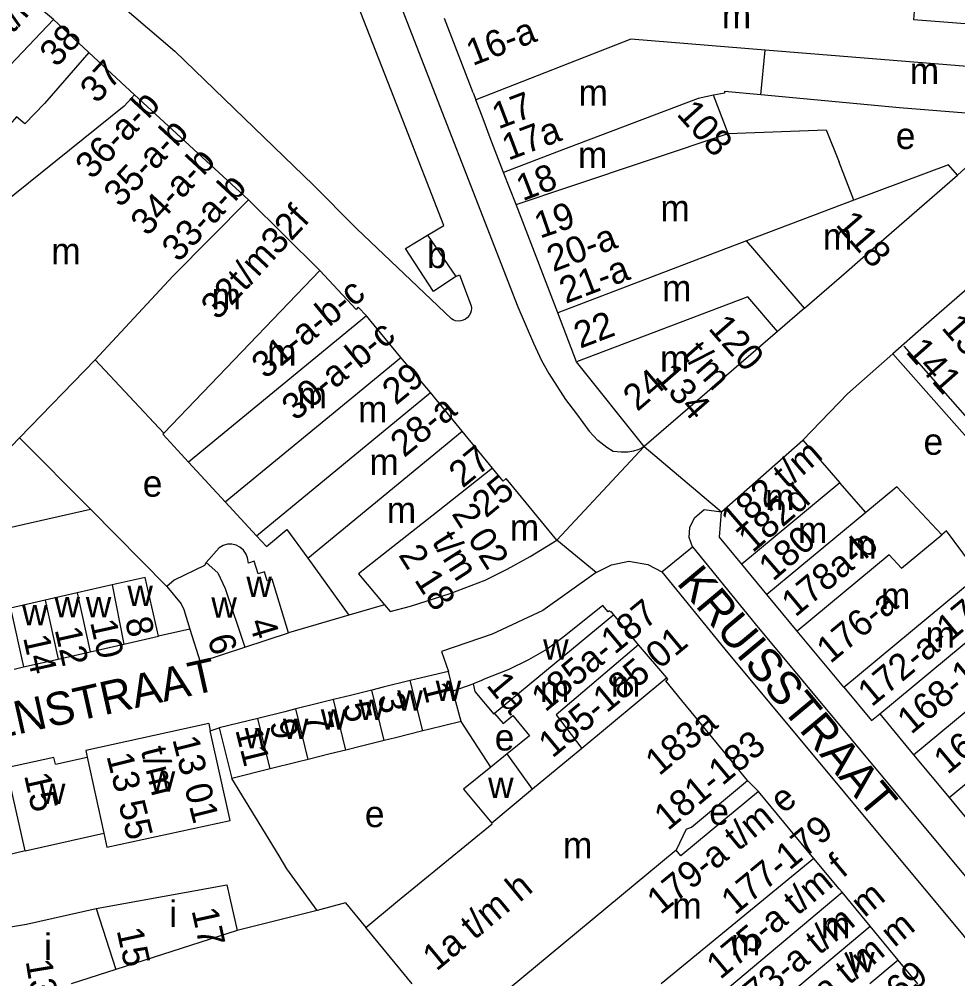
# Model space of a CAD drawing. Extents: x 159902 to 161769, y 383692 to 384875.
# Drawn here: x 160875.8 to 161018, y 384500.8 to 384646.1 of the extents above; entities that cross this region are included whole.
import ezdxf

# ---------------------------------------------------------------- set-up
doc = ezdxf.new("R2010")
doc.units = 0
for name, color, linetype in [('BLT_Basislijn', 7, 'Continuous'), ('BLT_Bebouwing', 7, 'Continuous'), ('BLT_Centroide', 7, 'Continuous'), ('BLT_Huisnummer', 7, 'Continuous'), ('BLT_Huisnummer_ tussenligend', 7, 'Continuous'), ('BLT_Huisnummer_reeks', 7, 'Continuous'), ('BLT_Onderverdeling_panden', 7, 'Continuous'), ('BLT_Plantopo', 7, 'Continuous'), ('BLT_Straatnaam', 7, 'Continuous'), ('BLT_Vlakafsluiter', 7, 'Continuous')]:
    doc.layers.add(name, color=color, linetype=linetype)

msp = doc.modelspace()

# ---------------------------------------------------------------- linework, layer by layer
at = {"layer": 'BLT_Basislijn'}
for p, q in [((160933.92, 384630.81), (160885.35, 384755.32)), ((160928.92, 384660.13), (160951.34, 384602.56)), ((161027.38, 384631.21), (161017.96, 384622.48)), ((160920.37, 384620.98), (160921.06, 384620.29)), ((160921.06, 384620.29), (160921.77, 384619.57)), ((160921.77, 384619.57), (160925.33, 384615.97)), ((160925.33, 384615.97), (160926.92, 384614.36)), ((160941.3, 384600.71), (160926.92, 384614.36)), ((160951.34, 384602.56), (160953.7, 384597.06)), ((160886.59, 384571.89), (160875.82, 384582.68)), ((160849.88, 384563.61), (160886.59, 384571.89)), ((160898.15, 384560.18), (160886.59, 384571.89)), ((160925.7, 384555.85), (160916.6, 384553.15)), ((160901.65, 384553.72), (160896.9, 384552.65)), ((160875.02, 384547.68), (160876.45, 384548.01)), ((160941.52, 384544.37), (160944.55, 384545.43)), ((160947.25, 384532.83), (160942.74, 384539.74)), ((160904.73, 384538.31), (160906.08, 384538.75)), ((160915.18, 384519.36), (160907.97, 384531.12)), ((160986.13, 384530.8), (160987.78, 384529.14)), ((160925.22, 384512.26), (160920.94, 384511.11)), ((160925.22, 384512.26), (160928.28, 384508.51)), ((160920.94, 384511.11), (160908.8, 384508.06))]:
    msp.add_line(p, q, dxfattribs=at)
for points in [[(160886.94, 384651.93), (160899.37, 384641.29), (160920.37, 384620.98)], [(160937.62, 384613.43), (160940.13, 384614.89), (160933.92, 384630.81)], [(160941.91, 384607.15), (160942.48, 384607.42), (160944.24, 384602.72)], [(160944.24, 384602.72), (160944.29, 384602.33), (160944.26, 384601.94), (160944.14, 384601.57), (160943.96, 384601.22), (160943.71, 384600.92), (160943.4, 384600.68), (160943.05, 384600.51), (160942.67, 384600.41), (160942.28, 384600.39), (160941.89, 384600.45), (160941.53, 384600.58), (160941.3, 384600.71)], [(160953.7, 384597.06), (160954.92, 384594.41), (160956.02, 384592.44), (160958.56, 384588.52), (160960.2, 384586.32)], [(161008.13, 384595.45), (161001.28, 384589.38), (160994.52, 384582.33)], [(160960.2, 384586.32), (160962.12, 384583.7), (160962.77, 384582.99), (160963.44, 384582.32)], [(160970.48, 384581.39), (160970, 384581.09), (160969.52, 384580.87), (160968.84, 384580.68), (160967.98, 384580.54), (160966.96, 384580.52), (160965.79, 384580.65), (160964.79, 384581.25), (160963.44, 384582.32)], [(160977.8, 384566.17), (160977.3, 384567.63), (160977.38, 384569.1), (160978.07, 384570.56), (160979.54, 384571.85), (160982.19, 384571.49)], [(160977.8, 384566.17), (160987.31, 384554.52), (161023.67, 384510.86), (161030, 384502.12), (161036.93, 384491.9), (161074.73, 384428.36), (161080.55, 384419.2)], [(160963.19, 384562.31), (160965.5, 384563.49), (160968.16, 384564.03), (160971.04, 384563.52), (160973.15, 384562.38)], [(160963.19, 384562.31), (160955.13, 384556.53), (160947.46, 384552.96), (160939.77, 384550.36), (160940.8, 384547.31)], [(160973.15, 384562.38), (160982.68, 384550.7), (161018.93, 384507.18), (161025.08, 384498.68), (161031.86, 384488.68), (161069.62, 384425.22), (161087.78, 384396.62), (161099.26, 384377.62)], [(160920.94, 384511.11), (160916.33, 384517.4), (160915.18, 384519.36)]]:
    msp.add_lwpolyline(points, dxfattribs=at)
at = {"layer": 'BLT_Bebouwing'}
for p, q in [((160886.34, 384641.08), (160880.96, 384646.06)), ((160893.27, 384634.67), (160886.34, 384641.08)), ((160910.51, 384618.77), (160893.27, 384634.67)), ((160944.57, 384634.97), (160944.94, 384633.91)), ((160983.22, 384628.83), (160980.99, 384634.59)), ((160947.15, 384628.16), (160946.05, 384631.03)), ((160949.17, 384622.92), (160947.15, 384628.16)), ((161002.26, 384618.72), (161000, 384624.44)), ((160951.06, 384618.03), (160949.17, 384622.92)), ((161004.88, 384611.11), (161017.96, 384622.48)), ((160957.37, 384601.64), (160951.06, 384618.03)), ((160937.62, 384613.43), (160941.91, 384607.15)), ((161001.12, 384607.84), (161004.88, 384611.11)), ((161025.93, 384610.96), (161012.86, 384599.57)), ((160941.91, 384607.15), (160938.57, 384604.89)), ((160994.78, 384602.33), (161001.12, 384607.84)), ((160994.78, 384602.33), (160990.69, 384598.83)), ((160928.87, 384600.64), (160928.41, 384601.21)), ((160933.6, 384594.88), (160928.87, 384600.64)), ((161012.86, 384599.57), (161008.13, 384595.45)), ((160990.69, 384598.83), (160970.48, 384581.39)), ((161008.13, 384595.45), (161023.09, 384578.49)), ((160887.31, 384594.51), (160875.82, 384582.68)), ((160897.69, 384583.43), (160887.31, 384594.51)), ((160938.07, 384589.58), (160933.6, 384594.88)), ((160942.9, 384583.7), (160938.07, 384589.58)), ((160947.48, 384578.12), (160942.9, 384583.7)), ((160982.19, 384571.49), (160994.52, 384582.33)), ((160994.52, 384582.33), (161000.13, 384575.89)), ((160906.97, 384573.03), (160901.45, 384579.02)), ((161004.06, 384571.4), (161000.13, 384575.89)), ((160906.97, 384573.03), (160911.71, 384567.88)), ((160911.71, 384567.88), (160913.24, 384566.23)), ((161016.27, 384568.64), (161015.58, 384568.03)), ((161021.22, 384561.97), (161016.27, 384568.64)), ((160989.07, 384558.99), (160985.27, 384563.58)), ((160889.87, 384560.42), (160884.56, 384559.21)), ((160884.56, 384559.21), (160879.71, 384558.11)), ((160993.67, 384553.43), (160989.07, 384558.99)), ((160969.61, 384551.36), (160965.85, 384555.91)), ((160901.65, 384553.72), (160903.21, 384548.76)), ((160909.96, 384550.97), (160916.6, 384553.15)), ((161000.72, 384544.92), (160993.67, 384553.43)), ((160886.55, 384550.3), (160891.63, 384551.45)), ((160881.7, 384549.2), (160886.55, 384550.3)), ((160903.21, 384548.76), (160909.96, 384550.97)), ((160940.8, 384547.31), (160935.88, 384546.15)), ((160941.52, 384544.37), (160940.8, 384547.31)), ((160935.02, 384545.93), (160930.91, 384544.91)), ((160935.88, 384546.15), (160935.02, 384545.93)), ((160929.2, 384544.49), (160925.95, 384543.68)), ((160930.91, 384544.91), (160929.2, 384544.49)), ((160923.38, 384543.04), (160920.98, 384542.45)), ((160925.95, 384543.68), (160923.38, 384543.04)), ((160916.01, 384541.22), (160911.91, 384540.2)), ((160917.68, 384541.63), (160916.01, 384541.22)), ((160920.98, 384542.45), (160917.68, 384541.63)), ((160911.91, 384540.2), (160906.08, 384538.75)), ((160942.74, 384539.74), (160937.77, 384538.51)), ((161006.16, 384540.89), (161011.29, 384534.7)), ((160904.52, 384539.42), (160904.73, 384538.31)), ((160936.92, 384538.3), (160932.81, 384537.28)), ((160937.77, 384538.51), (160936.92, 384538.3)), ((160931.09, 384536.85), (160927.84, 384536.04)), ((160932.81, 384537.28), (160931.09, 384536.85)), ((160925.27, 384535.41), (160922.87, 384534.81)), ((160927.84, 384536.04), (160925.27, 384535.41)), ((160986.13, 384530.8), (160981.58, 384536.35)), ((160881.01, 384534.27), (160873.86, 384532.72)), ((160881.27, 384533.26), (160886.07, 384534.34)), ((160919.56, 384533.99), (160917.91, 384533.58)), ((160922.87, 384534.81), (160919.56, 384533.99)), ((161011.29, 384534.7), (161016.67, 384528.21)), ((160913.82, 384532.57), (160907.97, 384531.12)), ((160917.91, 384533.58), (160913.82, 384532.57)), ((160996.19, 384518.99), (160987.78, 384529.14)), ((161016.67, 384528.21), (161020.45, 384523.64)), ((160976.85, 384523.41), (160975.31, 384520.26)), ((161000, 384514.4), (160996.19, 384518.99)), ((160887.45, 384511.42), (160907.26, 384515)), ((161000.45, 384513.86), (161000, 384514.4)), ((161004.71, 384508.72), (161000.45, 384513.86)), ((160908.8, 384508.06), (160890.42, 384502.17)), ((160935.33, 384500), (160928.28, 384508.51)), ((161008.97, 384503.58), (161004.71, 384508.72)), ((161011.94, 384500), (161008.97, 384503.58)), ((160890.42, 384502.17), (160883.63, 384500))]:
    msp.add_line(p, q, dxfattribs=at)
for points in [[(160973.65, 384653.51), (161011.61, 384650.35), (161011.27, 384646.09), (161023.71, 384645.1), (161023.19, 384638.65)], [(160880.96, 384646.06), (160874.66, 384651.39)], [(160944.57, 384634.97), (160940.23, 384646.21)], [(160988.13, 384634.65), (160982.63, 384635.17), (160982.66, 384634.93), (160980.99, 384634.59)], [(161027.38, 384631.21), (161009.15, 384632.67), (160988.13, 384634.65)], [(160946.05, 384631.03), (160944.94, 384633.91)], [(160983.22, 384628.83), (160998.05, 384629.37), (161000, 384624.44)], [(161017.96, 384622.48), (161016.56, 384624.08), (161002.26, 384618.72)], [(160921.32, 384608.04), (160910.51, 384618.77)], [(160938.57, 384604.89), (160934.3, 384611.38), (160937.62, 384613.43)], [(160928.41, 384601.21), (160927.13, 384602.48), (160926.81, 384602.15), (160921.32, 384608.04)], [(160960.23, 384594.23), (160957.37, 384601.64)], [(160970.48, 384581.39), (160960.23, 384594.23)], [(160901.45, 384579.02), (160897.55, 384583.25), (160897.69, 384583.43)], [(160875.82, 384582.68), (160870.77, 384577.48)], [(160957.23, 384567.18), (160949.55, 384576.54), (160949.09, 384576.16), (160947.48, 384578.12)], [(161015.58, 384568.03), (161008.76, 384575.3), (161004.06, 384571.4)], [(160985.27, 384563.58), (160981.9, 384567.64), (160982.19, 384571.49)], [(160913.24, 384566.23), (160916.35, 384568.84), (160919.51, 384564.45)], [(160916.6, 384553.15), (160914.13, 384561.27), (160913.37, 384561.04), (160912.94, 384562.39), (160911.99, 384562.09), (160911.39, 384564), (160910.51, 384563.72), (160910.37, 384564.54), (160910.17, 384565.09), (160909.76, 384565.7), (160909.23, 384566.16), (160908.63, 384566.46), (160908, 384566.59), (160907.35, 384566.58), (160906.68, 384566.39), (160906.08, 384566.03), (160904.11, 384563.81)], [(160931.14, 384557.43), (160931.96, 384556.42), (160935.07, 384557.21), (160941.08, 384559.1), (160946.38, 384561.16), (160949.72, 384562.81), (160953.22, 384564.72), (160957.23, 384567.18)], [(160919.51, 384564.45), (160925.7, 384555.85)], [(160904.11, 384563.81), (160903.83, 384563.38), (160899.25, 384561.13), (160898.15, 384560.18)], [(160896.9, 384552.65), (160894.87, 384561.55), (160889.87, 384560.42)], [(160898.15, 384560.18), (160900.31, 384557.56), (160900.72, 384556.7), (160901.65, 384553.72)], [(160879.71, 384558.11), (160874.46, 384556.92), (160876.45, 384548.01)], [(160931.14, 384557.43), (160925.7, 384555.85)], [(160964.21, 384557.31), (160958.36, 384552.61), (160955.77, 384550.7), (160952.92, 384549.05), (160949.94, 384547.62), (160945.95, 384546.06), (160945.98, 384545.98), (160944.55, 384545.43)], [(160965.85, 384555.91), (160965.5, 384556.33), (160965.42, 384556.27), (160965.21, 384556.51), (160965.01, 384556.35), (160964.21, 384557.31)], [(160891.63, 384551.45), (160896.9, 384552.65)], [(160973.9, 384546.33), (160969.61, 384551.36)], [(160876.45, 384548.01), (160881.7, 384549.2)], [(160981.58, 384536.35), (160976.17, 384542.93), (160973.74, 384545.87), (160974.06, 384546.14), (160973.9, 384546.33)], [(160942.74, 384539.74), (160941.8, 384543.25), (160941.52, 384544.37)], [(160944.55, 384545.43), (160944.82, 384544.29), (160947.68, 384540.85), (160947.81, 384540.96)], [(161000.72, 384544.92), (161004.92, 384539.86), (161006.16, 384540.89)], [(160947.81, 384540.96), (160949.09, 384539.42), (160950.55, 384540.63), (160953.1, 384537.55)], [(160904.52, 384539.42), (160885.85, 384535.36)], [(160888.6, 384522.81), (160889.07, 384520.68), (160907.74, 384524.73), (160904.73, 384538.31)], [(160906.08, 384538.75), (160907.28, 384533.9), (160907.97, 384531.12)], [(160953.1, 384537.55), (160949.71, 384534.82)], [(160881.27, 384533.26), (160881.01, 384534.27)], [(160885.85, 384535.36), (160886.07, 384534.34)], [(160949.71, 384534.82), (160947.25, 384532.83)], [(160947.25, 384532.83), (160943.11, 384529.49), (160947.38, 384524.35)], [(160976.85, 384523.41), (160977.62, 384523.75), (160986.13, 384530.8)], [(160987.78, 384529.14), (160983.93, 384525.94), (160982.54, 384524.79), (160976.03, 384519.39), (160975.31, 384520.26)], [(160928.28, 384508.51), (160933.09, 384512.5), (160947.46, 384524.25), (160947.38, 384524.35)], [(160876.67, 384520.14), (160888.6, 384522.81)], [(160876.67, 384520.14), (160869.89, 384518.53), (160869.5, 384520.27)], [(160907.26, 384515), (160907.71, 384512.95), (160908.8, 384508.06)], [(160867.05, 384507.42), (160876.87, 384509.04), (160887.45, 384511.42)]]:
    msp.add_lwpolyline(points, dxfattribs=at)
at = {"layer": 'BLT_Onderverdeling_panden'}
for p, q in [((160880.96, 384646.06), (160869.82, 384634.36)), ((160988.13, 384634.65), (160988.81, 384641.43)), ((161023.19, 384638.65), (160988.81, 384641.43)), ((160957.21, 384625.97), (160949.17, 384622.92)), ((160951.06, 384618.03), (160959.19, 384620.76)), ((160910.51, 384618.77), (160899.07, 384607.21)), ((161002.26, 384618.72), (160985.98, 384612.53)), ((160985.98, 384612.53), (160957.37, 384601.64)), ((160994.78, 384602.33), (160985.98, 384612.53)), ((160899.07, 384607.21), (160887.31, 384594.51)), ((160921.32, 384608.04), (160897.69, 384583.43)), ((160928.41, 384601.21), (160901.45, 384579.02)), ((160925.61, 384588.3), (160933.6, 384594.88)), ((160911.71, 384567.88), (160938.07, 384589.58)), ((160906.97, 384573.03), (160925.61, 384588.3)), ((160919.51, 384564.45), (160942.9, 384583.7)), ((161000.13, 384575.89), (160985.27, 384563.58)), ((161004.06, 384571.4), (160989.07, 384558.99)), ((161007.6, 384564.97), (160993.67, 384553.43)), ((161000.72, 384544.92), (161021.22, 384561.97)), ((160889.87, 384560.42), (160891.63, 384551.45)), ((160884.56, 384559.21), (160886.55, 384550.3)), ((160879.71, 384558.11), (160881.7, 384549.2)), ((160965.85, 384555.91), (160947.81, 384540.96)), ((161006.16, 384540.89), (161025.17, 384556.65)), ((161011.29, 384534.7), (161029.57, 384549.91)), ((160936.92, 384538.3), (160935.02, 384545.93)), ((160973.9, 384546.33), (160961, 384535.64)), ((160931.09, 384536.85), (160929.2, 384544.49)), ((160925.27, 384535.41), (160923.38, 384543.04)), ((161016.67, 384528.21), (161034.95, 384543.42)), ((160919.56, 384533.99), (160917.68, 384541.63)), ((160913.82, 384532.57), (160911.91, 384540.2)), ((160961, 384535.64), (160953.57, 384529.48)), ((160953.57, 384529.48), (160949.71, 384534.82)), ((160876.67, 384520.14), (160873.86, 384532.72)), ((160953.57, 384529.48), (160947.38, 384524.35)), ((160975.31, 384520.26), (160947.03, 384496.81)), ((160996.19, 384518.99), (160983.75, 384508.78)), ((160971.34, 384489.46), (161000.45, 384513.86)), ((160887.45, 384511.42), (160890.42, 384502.17)), ((160983.75, 384508.78), (160973.06, 384500)), ((160975.56, 384484.38), (161004.71, 384508.72)), ((161008.97, 384503.58), (161004.65, 384500))]:
    msp.add_line(p, q, dxfattribs=at)
for points in [[(160988.81, 384641.43), (160968.47, 384643.09), (160944.94, 384633.91)], [(160886.34, 384641.08), (160879.61, 384633.33), (160876.63, 384630.26), (160875.38, 384631.33), (160873.47, 384629.1), (160846.06, 384604.07)], [(160893.27, 384634.67), (160891.67, 384632.95), (160850.2, 384599.61)], [(160980.99, 384634.59), (160978.67, 384634.12), (160957.21, 384625.97)], [(160959.19, 384620.76), (160983.22, 384628.83)], [(160990.69, 384598.83), (160986.19, 384604.04), (160960.23, 384594.23)], [(160947.48, 384578.12), (160938.98, 384571.37), (160927.19, 384562.12), (160931.14, 384557.43)], [(161007.6, 384564.97), (161009.47, 384562.97), (161015.58, 384568.03)], [(160904.11, 384563.81), (160905.86, 384562.26), (160907, 384559.86), (160909.96, 384550.97)], [(160969.61, 384551.36), (160957.11, 384540.73), (160961, 384535.64)], [(160886.07, 384534.34), (160888.6, 384522.81)]]:
    msp.add_lwpolyline(points, dxfattribs=at)
at = {"layer": 'BLT_Plantopo'}
msp.add_lwpolyline([(161043.16, 384625.94), (161048.23, 384620.2), (161039.91, 384612.87), (161046.32, 384605.59), (161021.33, 384583.57), (161009.86, 384596.59)], dxfattribs=at)
at = {"layer": 'BLT_Vlakafsluiter'}
for p, q in [((160957.23, 384567.18), (160970.48, 384581.39)), ((160970.48, 384581.39), (160982.19, 384571.49)), ((160963.19, 384562.31), (160957.23, 384567.18)), ((160973.15, 384562.38), (160977.8, 384566.17))]:
    msp.add_line(p, q, dxfattribs=at)

# ---------------------------------------------------------------- texts
at = {"layer": 'BLT_Centroide'}
for s, p in [('m', (160982.23, 384644.72)), ('m', (161010.71, 384636.31)), ('m', (160960.52, 384633)), ('e', (161008.59, 384626.46)), ('m', (160960.44, 384623.58)), ('m', (160972.93, 384615.5)), ('m', (160997.54, 384611.22)), ('b', (160937.56, 384608.43)), ('m', (160880.64, 384609.01)), ('m', (160904.94, 384602.17)), ('m', (160973.18, 384603.38)), ('m', (160913.34, 384593.66)), ('m', (160972.87, 384592.72)), ('m', (160917.95, 384587.19)), ('m', (160927.12, 384585.06)), ('e', (161012.79, 384580.14)), ('m', (160928.84, 384577.09)), ('e', (160894.5, 384573.79)), ('m', (160988.79, 384571.75)), ('m', (160931.47, 384569.78)), ('m', (160950.11, 384567.14)), ('m', (160993.78, 384566.75)), ('m', (161001.23, 384564.38)), ('w', (160910.2, 384558.61)), ('w', (160892.17, 384557.25)), ('m', (161006.35, 384556.78)), ('w', (160876.21, 384554.32)), ('w', (160881.12, 384555.53)), ('w', (160885.87, 384555.53)), ('w', (160904.89, 384555.47)), ('m', (161013.1, 384550.91)), ('w', (160955.16, 384549.12)), ('w', (160938.88, 384542.83)), ('m', (160954.66, 384542.69)), ('m', (160965.42, 384543.5)), ('w', (160933.06, 384541.39)), ('w', (160927.23, 384539.95)), ('w', (160921.47, 384538.52)), ('w', (160915.73, 384537.09)), ('w', (160909.95, 384535.66)), ('e', (160947.83, 384535.34)), ('w', (160895.55, 384529.12)), ('w', (160946.82, 384528.16)), ('w', (160878.91, 384527.23)), ('e', (160928.15, 384523.73)), ('e', (160980.33, 384524.09)), ('m', (160958.16, 384519)), ('i', (160898.52, 384508.59)), ('m', (160974.74, 384509.84)), ('m', (160997.24, 384506.88)), ('i', (160879.55, 384503.59)), ('m', (160983.61, 384504.31)), ('w', (161001.51, 384501.72))]:
    msp.add_text(s, height=4, dxfattribs=at).set_placement(p)
at = {"layer": 'BLT_Huisnummer'}
for s, rotation, p in [('38', 47.1834, (160881.43, 384638.7)), ('37', 47.1834, (160887.55, 384633.2)), ('118', 310.8034, (160999.35, 384614.95)), ('22', 20.8229, (160960.76, 384596.19)), ('141', 311.4145, (161009.97, 384595.71)), ('29', 39.4634, (160932.86, 384587.54)), ('27', 39.4634, (160942.96, 384574.99)), ('180', 40.8236, (160989.99, 384560.87)), ('8', 282.5733, (160891.78, 384555.15)), ('4', 286.7687, (160910.55, 384554.79)), ('12', 282.5733, (160881.14, 384553.66)), ('6', 286.7687, (160904.26, 384552.36)), ('14', 282.5733, (160876.35, 384552.46)), ('1a', 309.6645, (160946.43, 384545.18)), ('1', 283.9268, (160936.83, 384545.2)), ('5', 283.9338, (160924.75, 384542.21)), ('9', 283.9268, (160913.68, 384539.6)), ('11', 283.9362, (160908.5, 384538.47)), ('15', 282.5733, (160876.5, 384531.58)), ('13', 279.388, (160876.74, 384503.44))]:
    msp.add_text(s, height=4, rotation=rotation, dxfattribs=at).set_placement(p)
at = {"layer": 'BLT_Huisnummer_ tussenligend'}
for s, rotation, p in [('10', 282.5733, (160886.5, 384554.79)), ('3', 283.9268, (160930.04, 384543.56)), ('7', 283.9338, (160918.99, 384540.61))]:
    msp.add_text(s, height=4, rotation=rotation, dxfattribs=at).set_placement(p)
at = {"layer": 'BLT_Huisnummer_reeks'}
for s, height, rotation, p in [('39-at/mg', 4, 49.5779, (160867.8, 384635.62)), ('16-a', 4, 21.1116, (160944.48, 384639.01)), ('36-a-b', 4, 47.1825, (160886.84, 384621.71)), ('17', 4, 20.7735, (160948.37, 384629.41)), ('108', 4, 311.6986, (160975.26, 384631.68)), ('35-a-b', 4, 47.1816, (160891.13, 384617.45)), ('17a', 4, 20.7735, (160949.88, 384624.67)), ('34-a-b', 4, 47.1816, (160895.2, 384613.11)), ('18', 4, 21.0765, (160952.06, 384618.52)), ('33-a-b', 4, 47.1816, (160899.93, 384609.17)), ('32t/m32f', 4, 47.1825, (160905.86, 384600.4)), ('19', 4, 18.9516, (160954.67, 384612.86)), ('20-a', 4, 20.8224, (160956.68, 384607.79)), ('21-a', 4, 20.8224, (160958.58, 384602.99)), ('31-a-b-c', 4, 39.3071, (160913.07, 384591.5)), ('120', 4, 311.085, (160980.06, 384599.22)), ('139-a t/m v', 4, 311.084, (161015.38, 384599.32)), ('30-a-b-c', 4, 39.3071, (160917.63, 384585.15)), ('t/m', 4, 311.085, (160976.12, 384595.21)), ('134', 4, 311.085, (160971.94, 384591.84)), ('24', 4, 40.8011, (160969.44, 384586.59)), ('28-a', 4, 39.4623, (160934.11, 384579.62)), ('182 t/m ', 4, 40.8249, (160984.26, 384568.07)), ('25', 4, 39.4653, (160946.49, 384570.46)), ('182d', 4, 40.8249, (160986.9, 384565.18)), ('2 02', 4, 302.5761, (160941.21, 384571.21)), ('t/m', 4, 302.5761, (160938.2, 384566.97)), ('178a-b', 4, 39.6443, (160993.37, 384555.44)), ('2 18', 4, 302.5761, (160933.15, 384564.95)), ('176-a', 4, 39.6458, (160998.68, 384548.4)), ('172-a-174', 4, 39.6443, (161004.93, 384541.84)), ('185a-187', 4, 39.6599, (160955.48, 384541.06)), ('185-185 01', 4, 39.6599, (160956.56, 384534.08)), ('168-170', 4, 39.7549, (161010.92, 384537.67)), ('166-a-b', 4, 39.759, (161016.44, 384531.6)), ('183a', 4, 39.6614, (160972.74, 384531.4)), ('13 01', 4, 284.1313, (160898.96, 384537.05)), ('181-183', 4, 39.6714, (160974.07, 384523.08)), ('t/m', 4, 284.1313, (160894.17, 384535.42)), ('13 55', 4, 284.1313, (160888.98, 384534.51)), ('179-a t/m e', 4, 39.3907, (160972.96, 384510.37)), ('177-179', 4, 39.3894, (160984.21, 384510.3)), ('175-a t/m f', 3.9999, 39.665, (160981.99, 384500.54)), ('1a t/m h', 4, 39.6626, (160938.99, 384501.8)), ('173-a t/m m', 4, 39.6574, (160985.31, 384494.56)), ('17', 4, 282.4867, (160901.87, 384511.12)), ('171-a t/m m', 4, 39.6561, (160989.83, 384490.04)), ('15', 4, 282.4965, (160890.52, 384508.1)), ('169', 4, 39.6676, (161006.9, 384495.05))]:
    msp.add_text(s, height=height, rotation=rotation, dxfattribs=at).set_placement(p)
at = {"layer": 'BLT_Straatnaam'}
for s, rotation, p in [('KRUISSTRAAT', 309.8876, (160975.25, 384560.68)), ('VAN KINSBERGENSTRAAT', 12.5698, (160822.26, 384525.88))]:
    msp.add_text(s, height=5, rotation=rotation, dxfattribs=at).set_placement(p)

doc.saveas('drawing.dxf')
